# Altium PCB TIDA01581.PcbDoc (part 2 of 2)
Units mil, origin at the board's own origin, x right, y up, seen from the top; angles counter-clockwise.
Board outline 3050 x 2610 mil, 2 copper layers (Top Layer, Bottom Layer), stack 62 mil thick; 135 components, 67 nets, 345 pads, 231 vias.
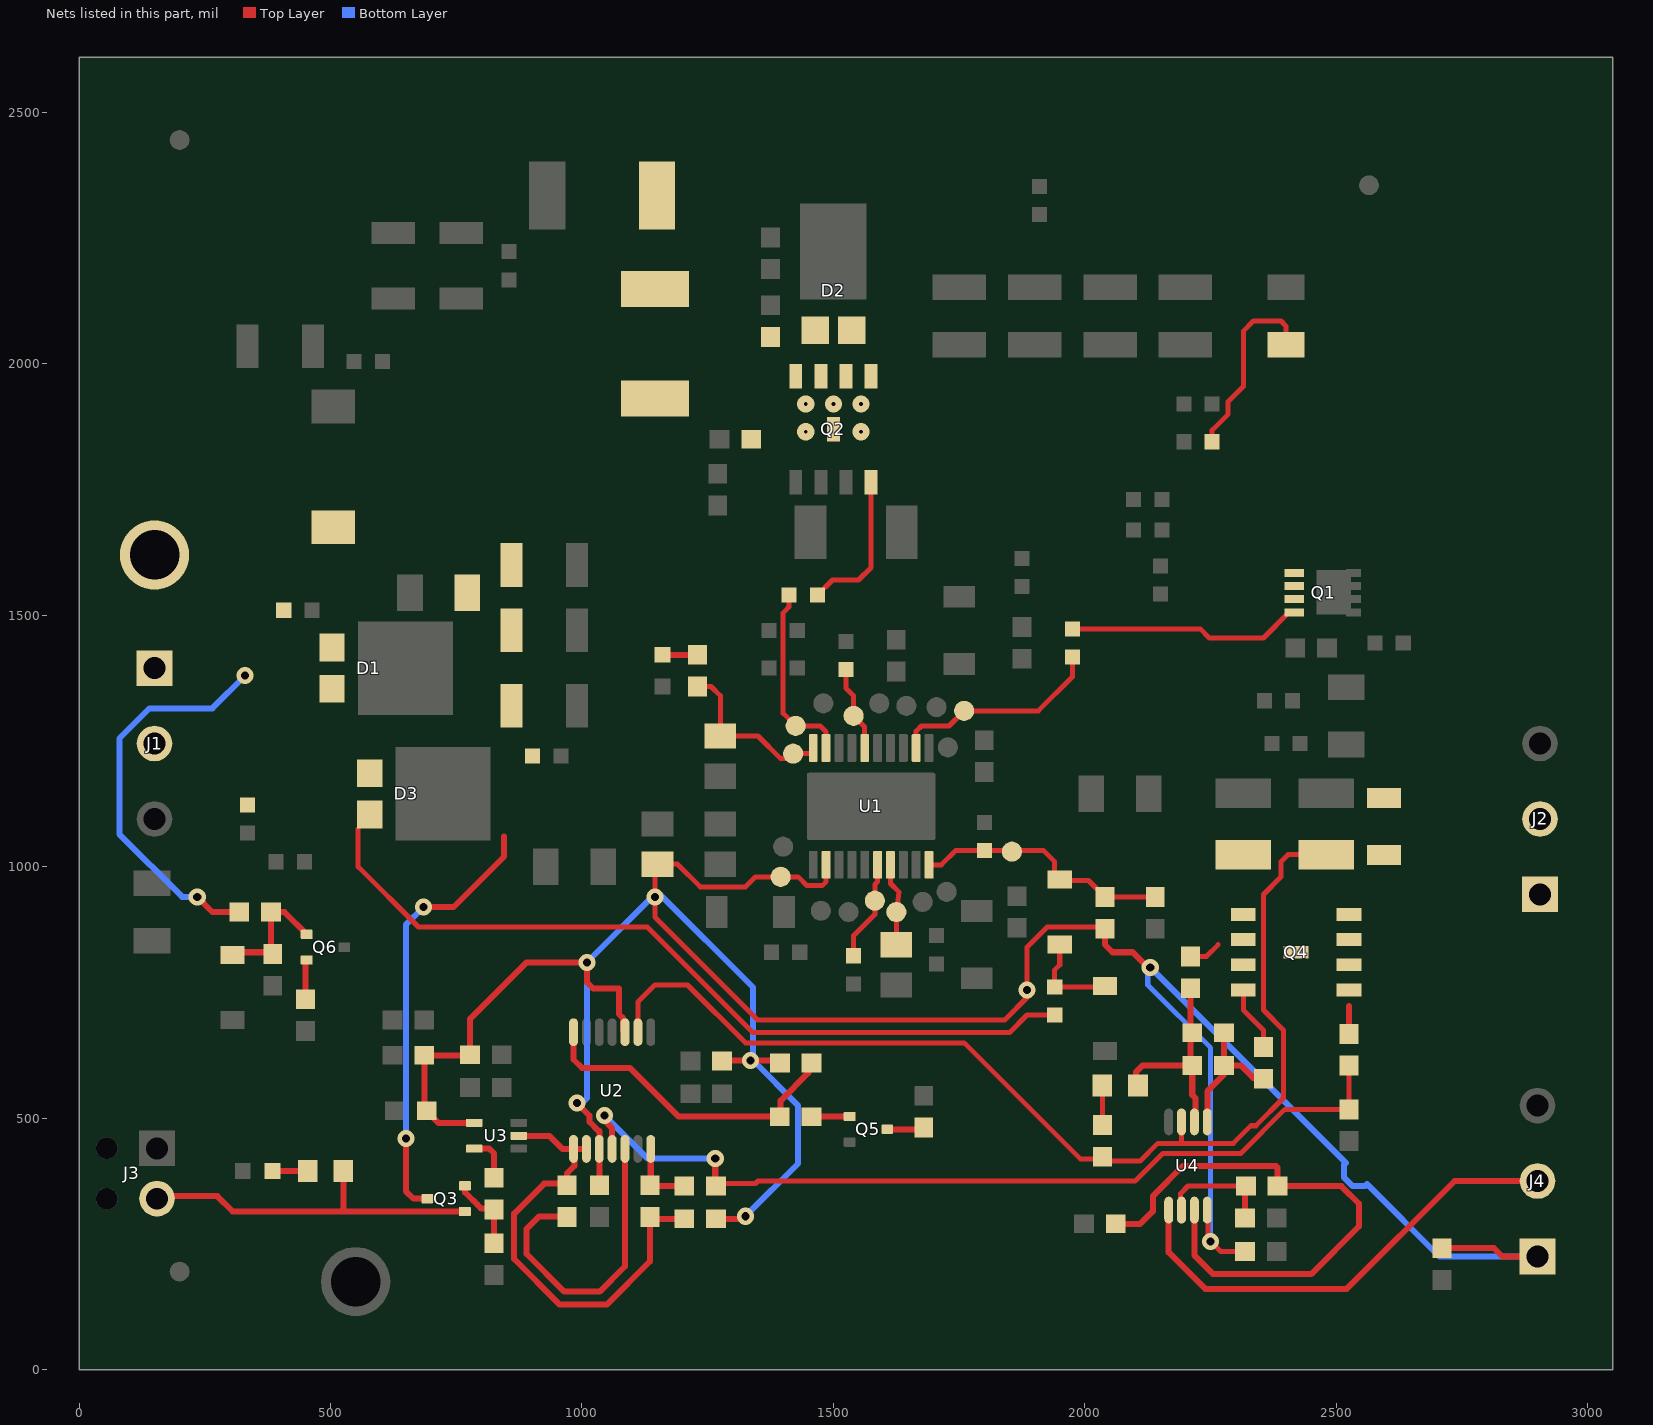
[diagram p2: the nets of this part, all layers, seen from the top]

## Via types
v1: diameter 34, hole 16, Top Layer to Bottom Layer, 203 vias
v2: diameter 34, hole 7.87, Top Layer to Bottom Layer, 11 vias
v3: diameter 19.68, hole 7.87, Top Layer to Bottom Layer, 11 vias
v4: diameter 19.68, hole 7.87, Top Layer to Bottom Layer, tented both sides, 6 vias

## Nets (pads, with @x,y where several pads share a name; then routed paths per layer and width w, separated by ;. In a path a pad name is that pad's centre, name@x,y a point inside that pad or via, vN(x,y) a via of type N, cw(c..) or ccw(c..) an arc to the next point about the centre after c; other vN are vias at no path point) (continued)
NetC38_1: C38.1 D4.1 pad.1@1855,1030 R16.2 R19.2 U1.10 | length 521.7
  Top Layer w10: U1.10@1690.16,1003.86 1714.68,1003.86 1742.82,1032 C38.1@1800,1032 1918,1032 1940,1010 1940,972.52 2007.03,972.52 R16.2@2040,939.55 R19.2@2140,939.55
NetC39_2: C39.2 pad.1@1625,910 U1.7 | length 168.1
  Top Layer w10: U1.7@1613.39,1003.86 1613.39,966.61 1630,950 pad.1@1625,910 1625,850 C39.2@1620,845
NetC42_1: C42.1 R21.1 R23.2 U2.4 | length 1785.7
  Top Layer w10: R21.1@1265,370 1345,370 1350,375 2100,375 2155,430 2310,430 2397.52,517.52 C42.1@2525,517.52 R23.2@2525,604.53
  Top Layer w12: v1(1045,505) 1045,495.03 1060,480.03 U2.4@1060,438.86 ; R21.1@1265,370 v1(1265,420)
  Bottom Layer w12: v1(1045,505) 1130,420 v1(1265,420)
NetC43_1: C43.1 R24.1 R36.2 U2.9 U4.3 | length 2195.6
  Top Layer w10: U2.9@1111.18,671.14 1111.18,731.18 1145,765 1210,765 1325,650 1760,650 1991.5,418.5 C43.1@2035,418.5 ; C43.1@2035,420 2040,415 2110,415 2145,450 2190,450 ; U4.3@2192.2,492.6 2192.2,452.2 2190,450 ; R36.2@2480,1023.98 2403.98,1023.98 2390,1010 2390,980 2355,945 2355,715 2395,675 2395,540 2340,485 2330,485 2295,450 2190,450
NetC43_2: C43.2 R33.2 | length 78.5
  Top Layer w10: C43.2@2035,486.5 R33.2@2035,565
NetC45_1: C45.1 R26.1 R31.2 U4.1 | length 265.6
  Top Layer w12: U4.1@2243.39,506.14 2243.39,553.39 2276.5,586.5 C45.1@2276.5,605 2309.98,605 2334.67,580.31 R26.1@2353.7,580.31 ; C45.1@2275,605 2276.5,606.5 R31.2@2276.5,670
NetC45_2: C45.2 R31.1 R33.1 R34.1 U4.2 | length 408.3
  Top Layer w12: R33.1@2101.5,555 2101.5,591.5 2115,605 C45.2@2213.5,605 2213.5,546.5 2220,540 U4.2@2220,505 ; C45.2@2210,608.5 R34.1@2210,758.5 R34.1@2210,760
NetD2_1: D2.1 D2.2 L3.2 Q2.5 Q2.6 Q2.7 Q2.8 Q2.9 R1.2 R3.2
  other v2: 1445,1865 1555,1865 1445,1920 1500,1920 1555,1920
NetD4_2: D4.2 D6.1 R18.1 | length 193.7
  Top Layer w10: D4.2@1950,850 D4.2@1950,845.53 1950,805 1940,795 R18.1@1940,761.05 2038.53,761.05 D6.1@2040,762.52
NetD5_2: D5.2 R17.2 | length 60.6
  Top Layer w12: D5.2@1170,1420 1171.5,1421.5 R17.2@1230,1421.5
NetD7_2: D7.2 R30.1 | length 64.6
  Top Layer w12: D7.2@390,395 R30.1@454.57,395
NetD8_1: D8.1 Q6.1 R42.1 R47.2 | length 240.5
  Top Layer w12: D8.1@310.53,830 381.5,830 R42.1@381.5,910 408.19,910 Q6.1@452.6,865.59
NetJ2_1: J2.1 Q4.5 Q4.6 Q4.7 Q4.8 Q4.9 R23.1 | length 55.3
  Top Layer w12: R23.1@2525,667.52 2525,722.8
NetJ2_2: J2.2 R24.2
NetJ3_2: J3.2 Q3.2 R30.2 | length 705.3
  Top Layer w12: J3.2@150,345 275,345 305.59,314.41 Q3.2@767.4,314.41 ; 525,320 525.43,320.43 R30.2@525.43,395
NetJ4_2: J4.2 U4.5 | length 935.1
  Top Layer w12: U4.5@2165,310 2166.61,308.39 2166.61,233.39 2240,160 2520,160 2735,375 J4.2@2900,375 J4.2@2905,375
NetL2_2: L2.2 L3.1
NetQ1_1: Q1.1 Q1.2 Q1.3 R2.2 R12.2 | length 380.2
  Top Layer w10: R12.2@2253,1845 2253,1868 2285,1900 2285,1925 2315,1955 2315,2065 2335,2085 2390,2085 2400,2075 R2.2@2400,2037.91
NetQ1_4: Q1.4 R8.1 | length 469.8
  Top Layer w10: R8.1@1975,1473 2229.5,1473 2247.5,1455 2355,1455 2406,1506 Q1.4@2416.25,1506
NetQ2_4: Q2.4 R7.1 | length 299.8
  Top Layer w10: R7.1@1468,1540 1498,1570 1550,1570 1575,1595 Q2.4@1575,1764.68 Q2.4@1575,1765
NetQ3_1: Q3.1 R25.2 R27.2 | length 139.8
  Top Layer w12: Q3.1@767.4,365.59 767.4,352.6 783.34,336.66 783.46,336.66 792.21,327.91 792.21,327.79 800,320 R25.2@810,320 ; R25.2@823.5,320 R25.2@825,318.5 R27.2@825,251.5 R27.2@825,250
NetQ4_1: Q4.1 Q4.2 Q4.3 R34.2 R37.2 | length 64.7
  Top Layer w10: R34.2@2210,821.5 2241.5,821.5 2265,845
NetQ4_4: Q4.4 R26.2 | length 130.1
  Top Layer w10: Q4.4@2315,755 2315,715 2355,675 R26.2@2355,641.5
NetQ5_1: Q5.1 R32.1 | length 76.3
  Top Layer w12: R32.1@1456.14,502.97 1531.65,502.97 Q5.1@1532.24,503.56
NetQ5_3: Q5.3 R28.2 | length 74.1
  Top Layer w12: Q5.3@1607.05,477.97 1676.14,477.97 R28.2@1679.64,481.47
NetQ6_2: Q6.2 R49.2 | length 79
  Top Layer w12: R49.2@450,736.5 450,811.81 Q6.2@452.6,814.41
NetR7_2: pad.1@1425,1280 R7.2 U1.19 | length 369.8
  Top Layer w10: 1410,1515 1400,1505 1400,1305 pad.1@1425,1280 1473.51,1280 1485.43,1268.08 U1.19@1485.43,1236.14 ; 1412,1517 R7.2@1412,1540
NetR8_2: pad.1@1760,1310 R8.2 U1.12 | length 428.1
  Top Layer w10: U1.12@1664.57,1236.14 1664.57,1269.57 1675,1280 1730,1280 pad.1@1760,1310 1907.5,1310 1975,1377.5 R8.2@1975,1417
NetR14_2: pad.1@1540,1300 R14.2 U1.16 | length 171.3
  Top Layer w10: R14.2@1525,1392 1525,1355 1540,1340 pad.1@1540,1300 1562.2,1277.8 U1.16@1562.2,1236.14
NetR15_1: pad.1@1582.5,932.5 R15.1 U1.6 | length 200.7
  Top Layer w10: R15.1@1540,823 1540,863 1582.5,905.5 pad.1@1582.5,932.5 1582.5,965 1587.8,970.3 U1.6@1587.8,1003.86
NetR20_1: R20.1 R22.2 R35.2 U2.1 U2.2 U3.2 | length 931.9
  Top Layer w12: U3.2@869.72,465 U3.2@874.29,465 935,465 961.14,438.86 U2.1@983.23,438.86 U2.2@1008.82,438.86 ; U2.1@985,425 985,405 970,390 970,370 925,370 865,310 865,220 955,130 1050,130 1135,215 R22.2@1135,303.5 1138.5,300 R20.1@1203.5,300
NetR21_2: R21.2 R22.1 U2.7 | length 140.6
  Top Layer w12: R22.1@1136.5,365 R21.2@1203.5,365 ; R22.1@1136.77,365.28 U2.7@1136.77,438.86
NetR25_1: R25.1 U3.4 | length 82.6
  Top Layer w12: U3.4@795,440 815,440 825,430 R25.1@825,381.5
NetR29_1: R29.1 R32.2 U2.14 | length 626.9
  Top Layer w12: U2.14@983.23,671.14 983.23,616.77 1000,600 1095,600 1192.03,502.97 R32.2@1393.15,502.97 ; R32.2@1395,520 1395,535 1450,590 1450,603.5 R29.1@1456.5,610
NetR35_1: R35.1 U2.5 | length 621.2
  Top Layer w12: R35.1@970,305 915,305 890,280 890,230 965,155 1035,155 1085.59,205.59 U2.5@1085.59,438.86
NetR38_1: R38.1 R39.2 U4.6 | length 250
  Top Layer w10: U4.6@2190,315 2190,350 2205.02,365.02 R38.1@2320.32,365.02 2318.5,363.21 R38.1@2310.29,355
  Top Layer w12: R39.2@2318.5,301.32 2318.5,363.21 2318.5,363.5 R38.1@2320,365
NetR38_2: R38.2 R40.1 U4.7 | length 1116.7
  Top Layer w12: R40.1@2061.5,290 2095,290 ; 2100,290 2110,290 2135,315 2135,345 2195,405 2380,405 2383.31,401.69 R38.2@2383.31,365.02 ; U4.7@2217.8,317.4 2217.8,227.2 2255,190 2450,190 2545,285 2545,330 2510,365 2420,365 ; R38.2@2385,365.02 2424.98,365.02
VBAT1: C3.1 D1.1 D1.2 J1.1 R42.2 TP1.1 | length 794.5
  Top Layer w12: v1(235,940) 265,910 R42.2@318.5,910
  Bottom Layer w12: v1(235,940) 205,940 80,1065 80,1255 140,1315 265,1315 v1(330,1380)
VBAT2: C2.1 D3.1 D3.2 J1.2 R18.2 | length 1611.2
  Top Layer w10: 555,1075 555,1000 675,880 1130,880 1340,670 1850,670 1885.05,705.05 R18.2@1940,705.05
VBATP: C5.1 C6.1 C7.1 C8.1 L1.1 l4.2 Q3.3 | length 869.7
  Top Layer w12: v1(650,460) 650,355 665,340 Q3.3@692.6,340 ; v1(685,920) 745,920 845,1020 845,1060
  Bottom Layer w12: v1(650,460) 650,885 v1(685,920)
VCC: C26.1 pad.1@1420,1225 R17.1 U1.20 | length 338.4
  Top Layer w10: R17.1@1230,1358.5 1256.5,1358.5 1275,1340 C26.1@1275,1270 ; C26.1@1275,1260 1350,1260 1395,1215 1410,1215 pad.1@1420,1225 1454.68,1225 1459.84,1230.16 U1.20@1459.84,1236.14
VREF: C29.2 C40.1 C41.1 C44.1 C46.1 J4.1 pad.1@1395,980 R16.1 R20.2 R29.2 R41.2 R43.2 R44.2 U1.2 U2.3 U2.10 U3.5 U4.8 | length 6224.7
  Top Layer w10: U1.2@1485.43,1003.86 1485.43,970.43 1477.5,962.5 1447.5,962.5 1430,980 pad.1@1395,980 1345,980 1325,960 1235,960 1190,1005 C29.2@1150,1005 1145,1000 1145,900 1350,695 1840,695 1890,745 1885,750 v1(1885,755) 1885,840 1925,880 R16.1@2035,880 ; U4.8@2245,325 2245,260 v1(2250,255) 2270,235 C44.1@2318.5,235
  Top Layer w12: U3.5@790,490 715,490 686.5,518.5 R41.2@686.5,625 776.26,625 R43.2@777.56,626.3 777.56,697.56 890,810 v1(1010,810) 1010,770 1021.96,758.04 1073.7,758.04 1073.7,707.05 1081.86,698.9 1081.86,674.87 U2.10@1085.59,671.14 ; v1@985,535 v1(990,530) 1015,505 1015,492.57 1032.57,475 1034.41,475 U2.3@1034.41,438.86 1035,438.27 C40.1@1035,366.5 ; R20.2@1266.5,300 v1@1315,300 ; R44.2@1278.51,613.54 1279.96,615 1340,615 1385,615 R29.2@1390,610 ; R16.1@2040,865 2040,845 2055,830 2095,830 2125,800 v1(2130,800) ; C46.1@2710,241.5 2813.5,241.5 2830,225 J4.1@2900,225
  Bottom Layer w10: v1@2125,800 2125,765 2250,640 v1(2250,255)
  Bottom Layer w12: v1(990,530) 1000,530 1010,540 v1(1010,810) 1140,940 v1(1145,940) 1150,940 1155,945 1340,760 1340,615 1430,525 1430,410 v1@1330,310 ; v1(2130,800) 2518.79,411.21 2515,407.43 2515,382.57 2532.57,365 2557.43,365 2561.21,368.79 2705,225 J4.1@2890,225
  other v1: 1325,305 1335,615
pads on no net: FID1.1 FID2.1 FID3.1 J3.MH1 J3.MH2 U1.21@1575,1120 U2.13 U3.1

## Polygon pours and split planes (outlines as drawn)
NetC1_1 on Top Layer "TOP_LAYER_NETC1_1_P010" (solid, remove dead copper, pour order 10): 1350,2210 1400,2210 1400,2090 1350,2090
NetJ2_1 on Top Layer "TOP_LAYER_NETJ2_1_P026" (solid, remove dead copper, pour order 26): 2370,970 2645,970 2645,1015 2650,1020 3025,1020 3025,735 3000,710 2370,710
LEDP on Top Layer "TOP_LAYER_LEDP_P025" (solid, remove dead copper, pour order 25): 2473.74,1365 2473.74,1207.48 2592.52,1207.48 2610,1190 3015,1190 3015,1290 2940,1365
NetJ2_2 on Top Layer "TOP_LAYER_NETJ2_2_P030" (solid, remove dead copper, pour order 30): 2552.83,1180 2552.83,1031.14 2553.98,1030 3020,1030 3020,1180
LEDP on Top Layer "TOP_LAYER_LEDP_P027" (solid, remove dead copper, pour order 27): 2407,1270 2417,1260 2417,1221 2566.64,1221 2567.64,1220 2566.26,1221.38 2566.26,1270
NetC43_1 on Top Layer "TOP_LAYER_NETC43_1_P029" (solid, remove dead copper, pour order 29): 2414.88,1063.5 2624.53,1063.5 2626.02,1065 2635,1056.02 2635,985 2415.43,985 2414.88,984.45
NetQ4_1 on Top Layer "TOP_LAYER_NETQ4_1_P024" (solid, remove dead copper, pour order 24): 2240,1065 2240,890 2280.08,782.2 2345,782.2 2345,970 2370,995 2380.12,1005.12 2380.12,1063.5
LEDN on Top Layer "TOP_LAYER_LEDN_P022" (solid, remove dead copper, pour order 22): 2065,1205 2065,1090 2550,1090 2545,1095 2545,1205 2390,1205 2390,1265 2340,1265 2340,1205
GND on Top Layer "TOP_LAYER_GND_P028" (solid, remove dead copper, pour order 28): 3025,-55 3025,1970.59 3051.05,2590 0,2590 0,1700 0,-55
NetC14_1 on Top Layer "TOP_LAYER_NETC14_1_P023" (solid, remove dead copper, pour order 23): 2525,1330 2590,1330 2590,1670 2590,1720 2575,1720 2510,1720 2460,1670 2460,1330
VBAT2 on Top Layer "TOP_LAYER_VBAT2_P021" (solid, remove dead copper, pour order 21): 70,1290 495,1290 545,1240 605,1240 605,1050 455,1065 327.5,1122.5 70,1135
VBAT1 on Top Layer "TOP_LAYER_VBAT1_P020" (solid, remove dead copper, pour order 20): 70,1700 238,1700 465,1473 525,1473 525,1320 70,1320
VBATP on Top Layer "TOP_LAYER_VBATP_P005" (solid, remove dead copper, pour order 5): 435,1775 435,1590 585,1590 745,1590 745,1297.86 830,1055 925,1055 925,1150 925,1285 925,1775
NetC9_1 on Top Layer "TOP_LAYER_NETC9_1_P006" (solid, remove dead copper, pour order 6): 560,1870 560,2175 590,2205 1265,2205 1265,2405 440,2405 440,1870
NetD2_1 on Top Layer "TOP_LAYER_NETD2_1_P007" (solid, remove dead copper, pour order 7): 1055,1820 1055,2100 1605,2100 1605,1820
NetC1_2 on Top Layer "TOP_LAYER_NETC1_2_P011" (solid, remove dead copper, pour order 11): 1350,2395 1595,2395 1670,2320 2330,2320 2455,2195 2455,2130 1350,2130
NetQ1_1 on Top Layer "TOP_LAYER_NETQ1_1_P018" (solid, remove dead copper, pour order 18): 2445,1520 2445,2060 2350,2060 2350,1520
NetL2_2 on Top Layer "TOP_LAYER_NETL2_2_P004" (solid, remove dead copper, pour order 4): 1055,2405 1260,2405 1260,2130 1240,2110 1055,2110
LEDN on Top Layer "TOP_LAYER_LEDN_P008" (solid, remove dead copper, pour order 8): 2320,1360 2365,1360 2365,1205 2360,1200 2320,1200
LEDP on Top Layer "TOP_LAYER_LEDP_P013" (solid, remove dead copper, pour order 13): 2400,1360 2400,1225 2450,1225 2450,1360
NetC24_1 on Top Layer "TOP_LAYER_NETC24_1_P009" (solid, remove dead copper, pour order 9): 1250,1870 1295,1870 1295,1765 1290,1760 1250,1760
NetC4_2 on Top Layer "TOP_LAYER_NETC4_2_P014" (solid, remove dead copper, pour order 14): 65,1140 210,1140 210,895 200,905 65,905
NetC4_1 on Top Layer "TOP_LAYER_NETC4_1_P015" (solid, remove dead copper, pour order 15): 565,1595 565,1547.5 632.5,1547.5 632.5,1495 565,1495 555,1495 555,1300 745,1300 745,1490 740,1495 685,1495 685,1595
NetC4_1 on Top Layer "TOP_LAYER_NETC4_1_P012" (solid, remove dead copper, pour order 12): 555,1495 555,1245 625,1245 630,1240 630,1050 825,1050 820,1055 820,1250 750,1250 770,1250 755,1495
NetC24_2 on Top Layer "TOP_LAYER_NETC24_2_P016" (solid, remove dead copper, pour order 16): 1340,1805 1545,1805 1545,1600 1420,1600 1420,1690 1245,1690 1245,1740 1340,1740
GND on Bottom Layer "BOTTOM_LAYER_GND_P019" (solid, remove dead copper, pour order 19): 0,-55 3050,-55 3050,1563.33 3050,2610 -2.39,2610 0,2565

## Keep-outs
Keep-Out Layer:
  text ".Layer_Name" at 577,-863.49 h60

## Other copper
Top Layer:
  text ".Layer_Name" at 577,-863.49 h60
Bottom Layer:
  rectangle net GND: 1505,1075 1645,1165
  rectangle net NetC14_1: 2470,1510 2510,1580
  rectangle net NetD2_1: 1420,1840 1580,1945
  rectangle net NetC1_2: 1445,2135 1555,2300
  text ".Layer_Name" at 577,-863.49 h60

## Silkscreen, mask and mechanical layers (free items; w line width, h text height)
Top Overlay:
  text "4.5V - 18V" at 185,1875 h30 r90
  text "INPUT VOLTAGE" at 140,1845 h30 r90
  text "LED+" at 2630,1245 h50
  text "REF-" at 2650,1110 h50
  text "MIR-" at 2655,940 h50
  text "*" at 1830,765 h40
  text "GND" at 2640,530 h50
  text "*" at 1720,280 h25
  text "FLT+" at 270,230 h72.83
  text "TIDA-01581" at 1395,110 h90
  text "5V" at 2890,105 h50
  text ".Layer_Name" at 577,-863.49 h60
Bottom Overlay:
  text ".Layer_Name" at 577,-863.49 h60
Top Paste:
  text ".Layer_Name" at 577,-863.49 h60
Bottom Paste:
  text ".Layer_Name" at 577,-863.49 h60
Top Solder:
  text ".Layer_Name" at 577,-863.49 h60
  text ".Layer_Name" at 577,-863.49 h60
Bottom Solder:
  rectangle: 1505,1075 1645,1165
  rectangle: 1445,2135 1555,2300
  rectangle: 1420,1840 1580,1945
  rectangle: 2470,1510 2510,1580
  text ".Layer_Name" at 577,-863.49 h60
Drill Guide:
  text ".Layer_Name" at 577,-863.49 h60
M1 Board Outline:
  the board outline again, w10
  text ".Layer_Name" at 577,-863.49 h60
M2 Board Dimensions:
  text ".Layer_Name" at 577,-863.49 h60
M3 3D STEP Top:
  text ".Layer_Name" at 577,-863.49 h60
M4 3D STEP Bottom:
  text ".Layer_Name" at 577,-863.49 h60
M5 Assembly Top:
  lines w10: -292,-935.17 6308,-935.17 ; -292,-731.83 6310,-731.83 ; -292,-528.5 -292,-1138.5 3713,-1138.5 6310,-1138.5 6310,-528.5 -291.5,-528.5 -291.5,-1138.5 1284,-1138.5 ; 2173,-1138.5 2173,-528.5 ; 3045,-75 3050,-70 ; 3440,-731.83 3440,-528.5 ; 4280,-731.83 4280,-528.5 ; 4902,-1145 4902,-942.17 ; 0,0 3050,0 3050,2610 0,2610 0,0
  text "COMPONENTS MARKED 'DNP' SHOULD NOT BE POPULATED." at 1153.5,-323.5 h60
  text "ASSEMBLY VARIANT:" at 1153,-439 h60
  text ".VariantName" at 2189,-439 h60
  text "PCB VIEWED FROM TOP SIDE" at -228.5,-660.67 h60
  text "BOARD #:" at 2248,-660.67 h60
  text ".PRJ_Number" at 2793.5,-660.67 h60
  text "REV:" at 3638,-660.67 h60
  text ".PCB_Rev" at 3929.5,-660.67 h60
  text "SVN REV:" at 4476,-660.67 h60
  text ".VersionControl_RevNumber" at 4982,-660.67 h60
  text "TID #:" at 2248,-864 h60
  text ".TID" at 2793.5,-864 h60
  text "PLOT NAME =" at -228.5,-1069.34 h60
  text ".plot_File_Name" at 577,-1069.34 h60
  text "GENERATED    :" at 2250,-1069.34 h60
  text ".Print_Date" at 3119.5,-1069.34 h60
  text ".Print_Time" at 3848.5,-1069.34 h60
  text "TEXAS INSTRUMENTS" at 5113,-1069.34 h60
M6 Assembly Bottom:
  lines w10: -292.5,-732.33 6309.5,-732.33 ; -290.5,-935.67 6309.5,-935.67 ; 1115.5,-1145.5 1115.5,-942.67 ; 1737.5,-732.33 1737.5,-529 ; 2577.5,-732.33 2577.5,-529 ; 3844.5,-1139 3844.5,-529 ; 4733.5,-1139 6309,-1139 6309,-529 -292.5,-529 -292.5,-1139 2304.5,-1139 6309.5,-1139 6309.5,-529
  text "COMPONENTS MARKED 'DNP' SHOULD NOT BE POPULATED." at 6102,-323 h60
  text ".VariantName" at 5058,-439 h60
  text "ASSEMBLY VARIANT:" at 6097,-439 h60
  text ".VersionControl_RevNumber" at 1035.5,-661.17 h60
  text "SVN REV:" at 1541.5,-661.17 h60
  text ".PCB_Rev" at 2088,-661.17 h60
  text "REV:" at 2379.5,-661.17 h60
  text ".PRJ_Number" at 3224,-661.17 h60
  text "BOARD #:" at 3769.5,-661.17 h60
  text "PCB VIEWED FROM BOTTOM SIDE" at 6246,-661.17 h60
  text ".TID" at 3224,-864.5 h60
  text "TID #:" at 3769.5,-864.5 h60
  text "TEXAS INSTRUMENTS" at 904.5,-1069.84 h60
  text ".Print_Time" at 2169,-1069.84 h60
  text ".Print_Date" at 2898,-1069.84 h60
  text "GENERATED    :" at 3767.5,-1069.84 h60
  text ".plot_File_Name" at 5440.5,-1069.84 h60
  text "PLOT NAME =" at 6246,-1069.84 h60
M9 Title Sheet:
  drawing of 57 lines, arcs and shapes, not listed
  text "1" at 739.84,8031.5 h70
  text "2" at 3235.5,8031.5 h70
  text "3" at 5724.84,8031.5 h70
  text "4" at 8231.51,8031.5 h70
  text "5" at 10730.5,8031.5 h70
  text "6" at 13235.5,8031.5 h70
  text "A" at -416.5,6888.5 h70
  text "A" at 14383.5,6888.5 h70
  text "B" at -416.5,4508.5 h70
  text "B" at 14383.5,4508.5 h70
  text "C" at -416.5,2133.5 h70
  text "C" at 14383.5,2133.5 h70
  text "PROJECT TITLE:" at 11343.5,272.5 h45
  text ".PRJ_Title" at 11393.5,139.17 h70
  text "DESIGNED FOR:" at 11343.5,-28.5 h45
  text ".PRJ_Customer" at 11393.5,-168.5 h70
  text "D" at -416.5,-236.5 h70
  text "D" at 14383.5,-236.5 h70
  text "FILE NAME:" at 11343.5,-328.5 h45
  text ".PCB_File_Name_No_Path" at 11393.5,-448.5 h70
  text "Texas Instruments (TI) and/or its licensors do not warrant the accuracy or completeness of this specification" at 6374,-610.34 h45
  text "ENGINEER:" at 11343.5,-618.5 h45
  text "LAYOUT BY:" at 12848.5,-618.5 h45
  text "or any information contained therein. TI and/or its licensors do not warrant that this design will meet" at 6329.01,-723 h45
  text ".PRJ_Engineer" at 11393.5,-773.49 h70
  text ".PCB_Layout" at 12899,-773.49 h70
  text "the specifications, will be suitable for your application or fit for any particular purpose, or will operate in" at 6329.01,-835.67 h45
  text ".Layer_Name" at 577,-863.49 h60
  text "ALTIUM DESIGNER VERSION:" at 12848.5,-928.5 h45
  text "an implementation. TI and/or its licensors do not warrant that the design is production worthy. You should" at 6329.01,-948.33 h45
  text "completely validate and test your design implementation to confirm the system functionality for your application." at 6374,-1061 h45
  text ".print_Scale" at 11393.5,-1061.83 h70
  text ".Application_BuildNumber" at 12899,-1061.83 h70
  text "1" at 739.84,-1268.5 h70
  text "2" at 3235.5,-1268.5 h70
  text "3" at 5724.84,-1268.5 h70
  text "4" at 8231.51,-1268.5 h70
  text "5" at 10730.5,-1268.5 h70
  text "6" at 13235.5,-1268.5 h70
M10 Fab Notes:
  drawing of 173 lines, arcs and shapes, not listed
  text "DESIGN INFORMATION" at 12378.02,6196 h60
  text "MIN. TRACK WIDTH:" at 11733.46,6016 h60
  text "8" at 12829.7,6016 h60
  text "MIL" at 12984.46,6016 h60
  text "7" at 12835,5885 h60
  text "MIN. CLEARANCE:" at 11733.46,5884 h60
  text "MIL" at 12984.46,5884 h60
  text "MIN. VIA PAD SIZE:" at 11733.46,5752 h60
  text "34" at 12799.71,5752 h60
  text "MIL" at 12984.46,5752 h60
  text "0.05mm (2MIL)" at 12428.46,5610.29 h60
  text "MINIMUM ANNULAR RING" at 11404.23,5606 h60
  text "EXTERNAL" at 13136.46,5606 h60
  text "PER" at 11604.23,5488 h60
  text "IPC-D-275 CLASS 2 LEVEL C" at 11824.23,5488 h60
  text "MIL, HOLES" at 13312.46,5375.71 h60
  text "+/-" at 12920,5375 h60
  text "+/-" at 13774,5375 h60
  text "REGISTRATION TOLERANCES:" at 11404.23,5370 h60
  text "METAL" at 12604,5370 h60
  text "5" at 13180.2,5370 h60
  text "3" at 14013.2,5370 h60
  text "MIL" at 14129.46,5370 h60
  text "+/-" at 13774,5257 h60
  text "HOLE SIZE TOLERANCE (UNLESS OTHERWISE SPECIFIED):" at 11404.23,5252 h60
  text "3" at 14013.2,5252 h60
  text "MIL" at 14129.46,5252 h60
  text "MATERIAL:" at 11329.46,5042.54 h60
  text "FR-4 High Tg" at 12315.9,4902.21 h60
  text "FR-408" at 11750.46,4893.64 h60
  text "OTHER" at 13238.46,4893.64 h60
  text "X" at 12161,4890 h60
  text "62 MIL (1.6mm) +/-10%" at 12070.56,4730.92 h60
  text "THICKNESS:" at 11404.23,4726.64 h60
  text "X" at 11942.4,4726.64 h60
  text "OTHER" at 13355.46,4726.64 h60
  text "TOLERANCE:" at 11404.23,4568.64 h60
  text "X" at 12243.53,4568.64 h60
  text "ANSI IPC-6012 TYPE 3 CLASS 2" at 12430.48,4568.64 h60
  text "OTHER +/-" at 12430.46,4412.64 h60
  text "BOW & TWIST:" at 11404.23,4255.64 h60
  text "X" at 12243.53,4255.64 h60
  text "ANSI IPC-6012 TYPE 3 CLASS 2" at 12430.48,4255.64 h60
  text "OTHER +/-" at 12430.46,4097.13 h60
  text "DRILLING:" at 11329.46,3958.64 h60
  text "REFERENCE:" at 11404.23,3841.64 h60
  text "X" at 12052.46,3841.64 h60
  text "AS SHOWN" at 12239.46,3841.64 h60
  text "X" at 12953.46,3841.64 h60
  text "NC_DRILL FILES" at 13090.46,3841.64 h60
  text "PTH COPPER THICKNESS:" at 11404.23,3683.64 h60
  text "X" at 12534.46,3683.64 h60
  text "20-30 um" at 12671.46,3683.64 h60
  text "OTHER" at 13388.46,3683.64 h60
  text "BOARD FINISH:" at 11329.46,3524.64 h60
  text "SILKSCREEN:" at 11484.68,3406.64 h60
  text "X" at 12433.46,3406.64 h60
  text "TOP" at 12559.46,3406.64 h60
  text "X" at 12943.46,3406.64 h60
  text "BOTTOM" at 13070.46,3406.64 h60
  text "SILKSCREEN COLOR:" at 11484.68,3239.64 h60
  text "X" at 12432.42,3239.64 h60
  text "WHITE" at 12559.46,3239.64 h60
  text "OTHER" at 13070.46,3239.64 h60
  text "X" at 12563.42,3080.44 h60
  text "GREEN" at 12690.46,3080.44 h60
  text "OTHER" at 13308.46,3080.44 h60
  text "SOLDER RESIST COLOR:" at 11484.68,3069.64 h60
  text "X" at 12563.42,2910.44 h60
  text "MATTE" at 12690.46,2910.44 h60
  text "SEMI-GLOSS" at 13308,2909.8 h60
  text "IMMERSION GOLD (ENIG)" at 12390.46,2721.92 h60
  text "ENEPIG" at 13728,2718.64 h60
  text "SURFACE FINISH:" at 11329.46,2717.64 h60
  text "X" at 12200,2710 h60
  text "IMM. TIN/SILVER OR EQUIV" at 11659,2560.64 h60
  text "OTHER" at 13090.46,2560.64 h60
  text "ARRAY/PANEL:" at 11329.46,2381.64 h60
  text "CUT AND TRIM PER M1 BOARD OUTLINE" at 12390.46,2377.35 h60
  text "X" at 12205,2375 h60
  text "N.C. ROUTE" at 12390.46,2225.64 h60
  text "V. SCORE" at 13256.46,2225.64 h60
  text "CERTIFICATION:" at 11329.46,2088.64 h60
  text "MATERIALS AND WORKMANSHIP FOR ALL PCBS" at 12054.46,2088.64 h60
  text "TO MEET OR EXCEED THE REQUIREMENTS OF:" at 12054.46,1990.64 h60
  text "X" at 11680.96,1854.13 h60
  text "ANSI IPC-A-600F CLASS ->" at 11819.96,1854.13 h60
  text "X" at 13459.02,1854.13 h60
  text "2" at 13577.96,1854.14 h60
  text "1" at 13262.96,1852.64 h60
  text "3" at 13931.96,1852.64 h60
  text "X" at 12495.02,1694.64 h60
  text "RoHS" at 12631.96,1694.64 h60
  text "OTHER" at 13276.36,1694.64 h60
  text "ALL BOARDS MUST MEET OR EXCEED UL94-V0 REQUIREMENTS." at 11357,1529 h60
  text "PCB MUST BEAR THE UL94V-0 UL REGISTERED MATERIAL ID NUMBER" at 11357,1409 h60
  text "ADDITIONAL REQUIREMENTS:" at 11329.46,1235.64 h60
  text "MICROSECTION:" at 11404.23,1120.64 h60
  text "YES" at 12309.96,1120.64 h60
  text "REQUIRED" at 13171.46,964.49 h60
  text "BARE BOARD ELEC. TEST:" at 11404.23,961.64 h60
  text "NONE" at 12709.96,961.64 h60
  text "PER ORDER" at 13763.46,961.64 h60
  text "X" at 12580,950 h60
  text ".Layer_Name" at 577,-863.49 h60
M11 Gerber Information:
  lines w10: -292,-935.17 6308,-935.17 ; -292,-731.83 6310,-731.83 ; -292,-528.5 -292,-1138.5 3713,-1138.5 6310,-1138.5 6310,-528.5 -291.5,-528.5 -291.5,-1138.5 1284,-1138.5 ; 2173,-1138.5 2173,-528.5 ; 3440,-731.83 3440,-528.5 ; 4280,-731.83 4280,-528.5 ; 4902,-1145 4902,-942.17
  text "ALL ARTWORK VIEWED FROM TOP SIDE" at -228.5,-660.67 h60
  text "BOARD #:" at 2248,-660.67 h60
  text ".PRJ_Number" at 2793.5,-660.67 h60
  text "REV:" at 3638,-660.67 h60
  text ".PCB_Rev" at 3929.5,-660.67 h60
  text "SVN REV:" at 4476,-660.67 h60
  text ".VersionControl_RevNumber" at 4982,-660.67 h60
  text "LAYER NAME =" at -228.5,-863.49 h60
  text "TID #:" at 2248,-864 h60
  text ".TID" at 2793.5,-864 h60
  text "PLOT NAME =" at -228.5,-1069.34 h60
  text ".plot_File_Name" at 577,-1069.34 h60
  text "GENERATED    :" at 2250,-1069.34 h60
  text ".Print_Date" at 3119.5,-1069.34 h60
  text ".Print_Time" at 3848.5,-1069.34 h60
  text "TEXAS INSTRUMENTS" at 5113,-1069.34 h60
M12 Stackup:
  drawing of 191 lines, arcs and shapes, not listed
  text "Layer" at 9757.5,7822.5 h60
  text "Name" at 10167.41,7822.5 h60
  text "Material" at 11097.16,7822.5 h60
  text "Thickness" at 11956.92,7822.5 h60
  text "Constant" at 12606.76,7822.5 h60
  text "Board Layer Stack" at 13176.62,7822.5 h60
  text "1" at 9757.5,7702.5 h60
  text "Top Overlay" at 10167.41,7702.5 h60
  text "2" at 9757.5,7582.5 h60
  text "Top Solder" at 10167.41,7582.5 h60
  text "Solder Resist" at 11097.16,7582.5 h60
  text "0.40mil" at 11956.92,7582.5 h60
  text "3.5" at 12606.76,7582.5 h60
  text "3" at 9757.5,7462.5 h60
  text "Top Layer" at 10167.41,7462.5 h60
  text "Copper" at 11097.16,7462.5 h60
  text "1.40mil" at 11956.92,7462.5 h60
  text "4" at 9757.5,7342.5 h60
  text "Dielectric1" at 10167.41,7342.5 h60
  text "FR-4" at 11097.16,7342.5 h60
  text "59.20mil" at 11956.92,7342.5 h60
  text "4.8" at 12606.76,7342.5 h60
  text "5" at 9757.5,7222.5 h60
  text "Bottom Layer" at 10167.41,7222.5 h60
  text "Copper" at 11097.16,7222.5 h60
  text "1.40mil" at 11956.92,7222.5 h60
  text "6" at 9757.5,7102.5 h60
  text "Bottom Solder" at 10167.41,7102.5 h60
  text "Solder Resist" at 11097.16,7102.5 h60
  text "0.40mil" at 11956.92,7102.5 h60
  text "3.5" at 12606.76,7102.5 h60
  text "7" at 9757.5,6982.5 h60
  text "Bottom Overlay" at 10167.41,6982.5 h60
  text ".Layer_Name" at 577,-863.49 h60
M13 Component Bodies Top:
  text ".Layer_Name" at 577,-863.49 h60
M14 Component Bodies Bottom:
  text ".Layer_Name" at 577,-863.49 h60
M15 Courtyards Top:
  text ".Layer_Name" at 577,-863.49 h60
M16 Courtyards Bottom:
  text ".Layer_Name" at 577,-863.49 h60
Drill Drawing:
  lines w10: 4481.76,2109.65 4526.04,2109.65 4526.04,2153.93 4481.76,2153.93 4481.76,2109.65 ; 4481.76,2253.55 4526.04,2253.55 4503.9,2209.27 4481.76,2253.55 ; 4481.76,2331.04 4503.9,2308.9 4526.04,2331.04 4503.9,2353.17 4481.76,2331.04 ; 4481.76,2408.52 4481.76,2419.59 4492.83,2430.66 4481.76,2441.73 4481.76,2452.8 4492.83,2452.8 4503.9,2441.73 4514.97,2452.8 4526.04,2452.8 4526.04,2441.73 4514.97,2430.66 4526.04,2419.59 4526.04,2408.52 4514.97,2408.52 4503.9,2419.59 4492.83,2408.52 4481.76,2408.52 ; 4481.76,2519.21 4492.83,2519.21 4503.9,2508.14 4514.97,2519.21 4526.04,2519.21 4514.97,2530.28 4526.04,2541.35 4514.97,2541.35 4503.9,2552.42 4492.83,2541.35 4481.76,2541.35 4492.83,2530.28 4481.76,2519.21
  lines w12: 4441,2079.77 7553.94,2079.77 ; 4441,2577.88 7553.94,2577.88 ; 4756.63,1980.14 4756.63,2677.5 ; 5073.82,1980.14 5073.82,2677.5 ; 5695.56,1980.14 5695.56,2677.5 ; 5939.88,1980.14 5939.88,2677.5 ; 6300.22,1980.14 6300.22,2677.5 ; 7009.73,1980.14 7009.73,2677.5 ; 4441,1980.14 7553.94,1980.14 7553.94,2677.5 4441,2677.5 4441,1980.14
  text "Symbol" at 4500.77,2607.76 h72
  text "Quantity" at 4786.52,2607.76 h72
  text "Finished Hole Size" at 5103.7,2607.76 h72
  text "Plated" at 5725.45,2607.76 h72
  text "Hole Type" at 5969.77,2607.76 h72
  text "Drill Layer Pair" at 6330.11,2607.76 h72
  text "Hole Tolerance" at 7039.62,2607.76 h72
  text "2" at 4786.52,2508.14 h60
  text "43.31mil (1.100mm)" at 5103.7,2508.14 h60
  text "NPTH" at 5725.45,2508.14 h60
  text "Round" at 5969.77,2508.14 h60
  text "Top Layer - Bottom Layer" at 6330.11,2508.14 h60
  text "28" at 4786.52,2408.52 h60
  text "7.87mil (0.200mm)" at 5103.7,2408.52 h60
  text "PTH" at 5725.45,2408.52 h60
  text "Round" at 5969.77,2408.52 h60
  text "Top Layer - Bottom Layer" at 6330.11,2408.52 h60
  text "203" at 4786.52,2308.9 h60
  text "16.00mil (0.406mm)" at 5103.7,2308.9 h60
  text "PTH" at 5725.45,2308.9 h60
  text "Round" at 5969.77,2308.9 h60
  text "Top Layer - Bottom Layer" at 6330.11,2308.9 h60
  text "11" at 4786.52,2209.27 h60
  text "43.31mil (1.100mm)" at 5103.7,2209.27 h60
  text "PTH" at 5725.45,2209.27 h60
  text "Round" at 5969.77,2209.27 h60
  text "Top Layer - Bottom Layer" at 6330.11,2209.27 h60
  text "2" at 4786.52,2109.65 h60
  text "98.43mil (2.500mm)" at 5103.7,2109.65 h60
  text "PTH" at 5725.45,2109.65 h60
  text "Round" at 5969.77,2109.65 h60
  text "Top Layer - Bottom Layer" at 6330.11,2109.65 h60
  text "246 Total" at 4786.52,2010.03 h60
  text ".Layer_Name" at 577,-863.49 h60
M17 Embedded Cavity:
  text ".Layer_Name" at 577,-863.49 h60
M18 Embedded Assembly:
  text ".Layer_Name" at 577,-863.49 h60
M19 Embedded Keepout:
  text ".Layer_Name" at 577,-863.49 h60

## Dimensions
3050,2610 to 3050,0 on M2 Board Dimensions
3050,2610 to 0,2610 on M2 Board Dimensions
